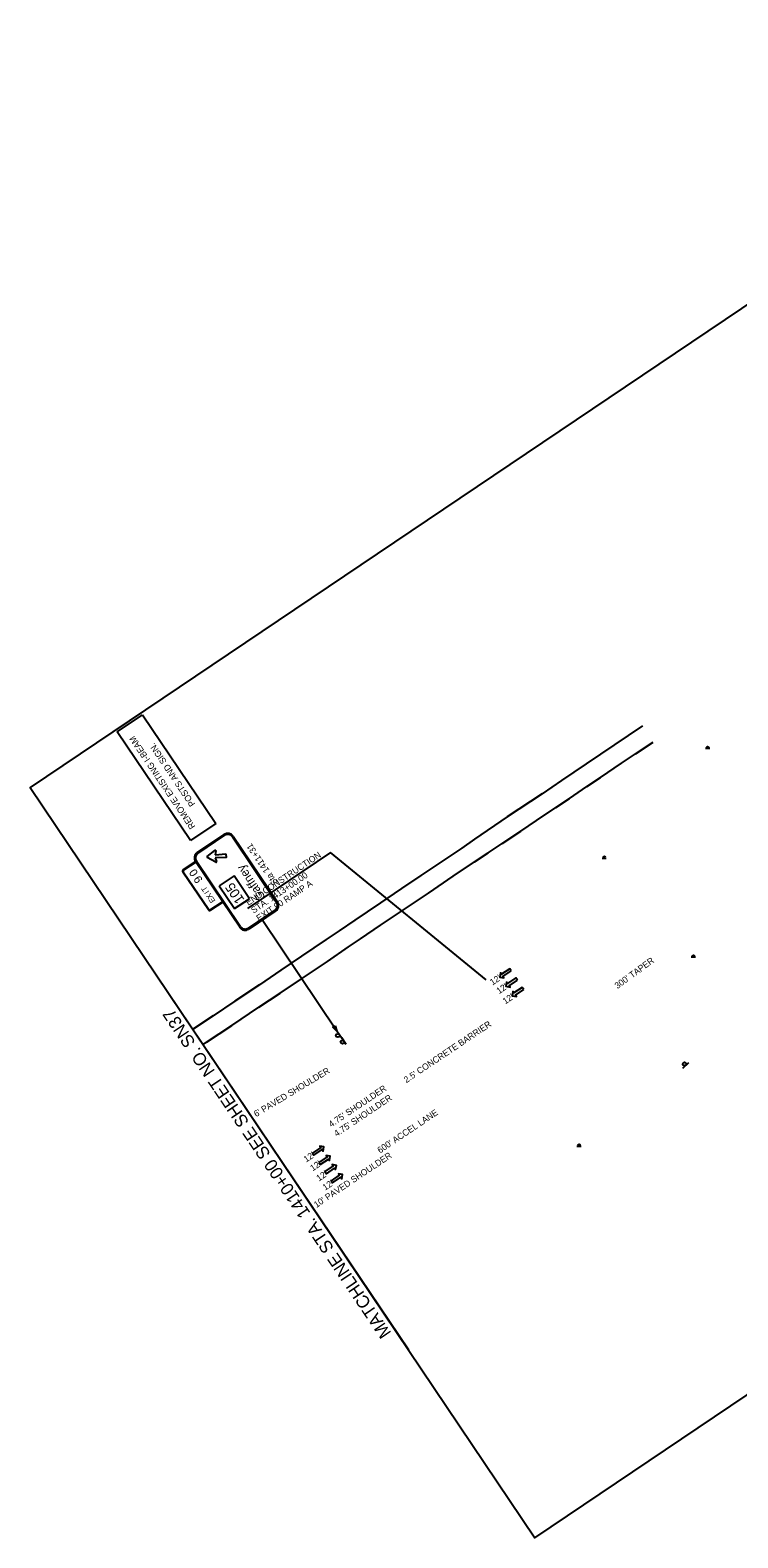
# Model space of a CAD drawing. Extents: x 1789464 to 1791208, y 1183240 to 1184943.
# Drawn here: x 1789464 to 1790247, y 1183240 to 1184907 of the extents above; entities that cross this region are included whole.
import ezdxf

# ---------------------------------------------------------------- set-up
doc = ezdxf.new("R2010")
doc.units = 0
for name, color, linetype in [('RD_EX_Road', 7, 'Continuous'), ('RD_PD_Final_LnLine', 7, 'Continuous'), ('RD_PD_Final_TX', 7, 'Continuous'), ('RD_SHT_MatchLine', 7, 'Continuous'), ('RD_SHT_ShtClip', 7, 'Continuous'), ('SN_P_Signs', 7, 'Continuous')]:
    doc.layers.add(name, color=color, linetype=linetype)

# ---------------------------------------------------------------- blocks, each defined once
blk = doc.blocks.new('SARRW2')
at = {"layer": 'RD_PD_Final_LnLine'}
blk.add_lwpolyline([(-12, 1.2), (-12, -1.2), (-2.8, -1.2), (-2.8, -2.8), (0, 0), (-2.8, 2.8), (-2.8, 1.2)], close=True, dxfattribs=at)

msp = doc.modelspace()

# ---------------------------------------------------------------- linework, layer by layer
at = {"layer": 'RD_EX_Road'}
for points in [[(1790141.7, 1184138), (1790079.6, 1184096.1), (1790052.1, 1184077.6), (1790030.8, 1184063.1), (1789992.1, 1184037.5), (1789955.9, 1184012.9), (1789941.8, 1184003), (1789919.8, 1183988.2), (1789896.7, 1183972.6), (1789875.2, 1183958.1), (1789852.1, 1183942.6), (1789837.3, 1183932.5), (1789823.4, 1183923.2), (1789806.2, 1183911.6), (1789791.8, 1183901.8), (1789764.7, 1183883.4), (1789741.7, 1183868), (1789718.1, 1183851.9), (1789690.8, 1183833.5), (1789666.8, 1183817.5), (1789645.1, 1183803), (1789644.3, 1183802.4)], [(1789655.6, 1183785.7), (1789659.4, 1183788.3), (1789687.3, 1183806.9), (1789717.4, 1183827), (1789740.9, 1183842.6), (1789764.4, 1183858.3), (1789793.2, 1183877.7), (1789816.4, 1183893.6), (1789829.8, 1183902.6), (1789852, 1183917.6), (1789876.2, 1183933.8), (1789905, 1183953.1), (1789932.3, 1183971.9), (1789956.1, 1183987.8), (1789970.9, 1183997.7), (1789986.7, 1184008), (1790007.3, 1184021.7), (1790024.5, 1184033.5), (1790045.9, 1184048), (1790060.9, 1184057.9), (1790080.3, 1184071.1), (1790095.4, 1184081.1), (1790118.6, 1184096.8), (1790133.9, 1184107), (1790153.7, 1184120.2)]]:
    msp.add_lwpolyline(points, dxfattribs=at)
at = {"layer": 'RD_PD_Final_TX'}
for p, q in [((1789796.6, 1183998), (1789704.8, 1183936.2)), ((1789969, 1183857.4), (1789796.6, 1183998))]:
    msp.add_line(p, q, dxfattribs=at)
at = {"layer": 'RD_SHT_MatchLine'}
msp.add_lwpolyline([(1789883.2, 1183447.6), (1789743.6, 1183655), (1789603.9, 1183862.4)], dxfattribs=at)
at = {"layer": 'RD_SHT_ShtClip'}
msp.add_lwpolyline([(1790601, 1183629.5), (1790542.4, 1183716.6), (1791208.5, 1184165), (1790708.7, 1184907.4), (1790708.7, 1184907.4), (1789464.3, 1184069.8), (1790022.8, 1183240.2)], close=True, dxfattribs=at)
at = {"layer": 'SN_P_Signs'}
for p, q in [((1789560.7, 1184131.5), (1789588.6, 1184150.3)), ((1789588.6, 1184150.3), (1789669.6, 1184030)), ((1789641.7, 1184011.2), (1789560.7, 1184131.5)), ((1790211.7, 1184113.3), (1790216.2, 1184113.3)), ((1789669.6, 1184030), (1789641.7, 1184011.2)), ((1790097.3, 1183991.9), (1790101.8, 1183991.9)), ((1789689.9, 1183972.3), (1789673.6, 1183961.3)), ((1789706.9, 1183947), (1789689.9, 1183972.3)), ((1789673.6, 1183961.3), (1789690.6, 1183936)), ((1789690.6, 1183936), (1789706.9, 1183947)), ((1789803.8, 1183800.5), (1789721.1, 1183923.5)), ((1790195.8, 1183882.6), (1790200.3, 1183882.6)), ((1789808.9, 1183793.1), (1789803.8, 1183800.5)), ((1789814, 1183785.9), (1789809, 1183793.3)), ((1790186.5, 1183759.6), (1790192.9, 1183766)), ((1790069.3, 1183673.5), (1790073.8, 1183673.5))]:
    msp.add_line(p, q, dxfattribs=at)
for points in [[(1789649.2, 1183998), (1789679.1, 1184018.1)], [(1789649.9, 1183997), (1789679.7, 1184017.1)], [(1789688.1, 1184015.5), (1789737, 1183942.8)], [(1789689.1, 1184016.2), (1789738, 1183943.5)], [(1789660.2, 1183993.7), (1789668.8, 1184000.4)], [(1789669.7, 1183999.8), (1789669, 1183995.4)], [(1789669, 1183995.4), (1789680.8, 1183996.7)], [(1789680.8, 1183996.7), (1789681.1, 1183992.6), (1789669.2, 1183992.2)], [(1789633.8, 1183979), (1789647.2, 1183988), (1789647.6, 1183987.5)], [(1789647.6, 1183987.5), (1789634.1, 1183978.5)], [(1789696.2, 1183915.4), (1789647.2, 1183988)], [(1789697.2, 1183916), (1789648.2, 1183988.7)], [(1789669.7, 1183987.3), (1789660.3, 1183992.7)], [(1789669.2, 1183992.2), (1789670.5, 1183988)], [(1789661.5, 1183934.7), (1789633.3, 1183976.5)], [(1789633.8, 1183976.8), (1789662, 1183935)], [(1789663.6, 1183934.7), (1789677.1, 1183943.7), (1789677.4, 1183943.2), (1789664, 1183934.2)], [(1789735.4, 1183934.5), (1789705.5, 1183914.4)], [(1789736, 1183933.5), (1789706.2, 1183913.4)]]:
    msp.add_lwpolyline(points, dxfattribs=at)
msp.add_lwpolyline([(1789801.7, 1183806.5), (1789803.8, 1183800.5), (1789799.1, 1183804.8)], close=True, dxfattribs=at)
for centre, radius in [((1790213.9, 1184114.3), 1), ((1790099.6, 1183992.9), 1), ((1790198.1, 1183883.6), 1), ((1789804.7, 1183795.7), 2), ((1789809.8, 1183788.5), 2), ((1790188.3, 1183764.2), 2), ((1790071.6, 1183674.5), 1)]:
    msp.add_circle(centre, radius, dxfattribs=at)
for centre, radius, start, end in [((1789683.1, 1184012.1), 7.2, 33.9476, 123.9476), ((1789683.1, 1184012.1), 6, 33.9476, 123.9476), ((1789653.2, 1183992), 7.2, 123.9476, 213.9476), ((1789653.2, 1183992), 6, 123.9476, 213.9476), ((1789669.1, 1183999.9), 0.6, 350.5015, 127.967), ((1789660.6, 1183993.2), 0.6, 127.967, 239.9283), ((1789670, 1183987.8), 0.6, 239.9283, 17.3937), ((1789634.8, 1183977.5), 1.8, 123.9476, 213.9476), ((1789634.8, 1183977.5), 1.2, 123.9476, 213.9476), ((1789663, 1183935.7), 1.8, 213.9476, 303.9476), ((1789663, 1183935.7), 1.2, 213.9476, 303.9476), ((1789732, 1183939.5), 6, 303.9476, 33.9476), ((1789732, 1183939.5), 7.2, 303.9476, 33.9476), ((1789702.1, 1183919.4), 7.2, 213.9476, 303.9476), ((1789702.1, 1183919.4), 6, 213.9476, 303.9476)]:
    msp.add_arc(centre, radius, start, end, dxfattribs=at)

# ---------------------------------------------------------------- block references
at = {"layer": 'RD_PD_Final_LnLine', "xscale": 1.1999999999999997}
for p, yscale, rotation in [((1789983.8, 1183860.3), 1.2000000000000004, -146.05256015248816), ((1789990.6, 1183850.1), 1.2000000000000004, -146.05256015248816), ((1789997.6, 1183839.7), 1.2000000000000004, -146.05256015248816), ((1789789.4, 1183672.6), 1.2, 33.94743984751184), ((1789796.4, 1183662.2), 1.2, 33.94743984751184), ((1789803.2, 1183652.1), 1.2, 33.94743984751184), ((1789810, 1183642), 1.2, 33.94743984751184)]:
    msp.add_blockref('SARRW2', p, dxfattribs=dict(at, yscale=yscale, rotation=rotation))

# ---------------------------------------------------------------- texts
at = {"layer": 'RD_PD_Final_TX'}
for s, rotation, p in [('END CONSTRUCTION', 33.9476, (1789705.8, 1183939.1)), ('STA. 1413+00.00', 33.9476, (1789711.6, 1183930.4)), ('EXIT 90 RAMP A', 33.9476, (1789717.5, 1183921.7)), ("300' TAPER", 36.2382, (1790114.1, 1183846.9)), ("12'", 33.9474, (1789975.9, 1183850.9)), ("12'", 33.9474, (1789983.1, 1183841.3)), ("12'", 33.9474, (1789990, 1183830)), ("2.5' CONCRETE BARRIER", 33.9474, (1789880.6, 1183742.9)), ("6' PAVED SHOULDER", 31.1375, (1789714.4, 1183705.3)), ("4.75' SHOULDER", 33.9474, (1789797.4, 1183693.9)), ("4.75' SHOULDER", 33.9474, (1789803.4, 1183683.5)), ("600' ACCEL LANE", 33.9476, (1789851.4, 1183665.1)), ("12'", 33.9474, (1789769.8, 1183655.1)), ("10' PAVED SHOULDER", 33.9474, (1789781.2, 1183604.9)), ("12'", 33.9474, (1789777, 1183645.4)), ("12'", 33.9474, (1789783.9, 1183634.2)), ("12'", 33.9474, (1789790.8, 1183624))]:
    msp.add_text(s, height=7, rotation=rotation, dxfattribs=at).set_placement(p)
at = {"layer": 'RD_SHT_MatchLine'}
msp.add_text('MATCHLINE STA. 1410+00 SEE SHEET NO. SN37', height=14, rotation=123.9476, dxfattribs=at).set_placement((1789864.3, 1183466.7))
at = {"layer": 'SN_P_Signs'}
for s, height, rotation, p in [('REMOVE EXISTING I-BEAM', 7, 123.9477, (1789647.4, 1184026.8)), ('POSTS AND SIGN.', 7, 123.9477, (1789647.4, 1184051.8)), ('Sta 1411+31', 7, 123.9477, (1789738.8, 1183964.5)), ('0', 9, 123.9476, (1789650.7, 1183975.4)), ('Gaffney', 9.6, 123.9476, (1789725.3, 1183948.4)), ('9', 9, 123.9476, (1789655.7, 1183967.9)), ('105', 10.8, 123.9476, (1789701.8, 1183945.9)), ('T', 6, 123.9476, (1789661.1, 1183957.2)), ('I', 6, 123.9476, (1789662.8, 1183954.7)), ('X', 6, 123.9476, (1789666.6, 1183949.1)), ('E', 6, 123.9476, (1789669.5, 1183944.8))]:
    msp.add_text(s, height=height, rotation=rotation, dxfattribs=at).set_placement(p)

doc.saveas('drawing.dxf')
